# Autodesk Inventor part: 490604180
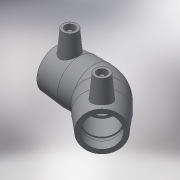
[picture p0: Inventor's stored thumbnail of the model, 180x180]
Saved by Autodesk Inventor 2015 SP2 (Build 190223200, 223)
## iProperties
Created: 2017-06
Part Number: 490604180
Material: Generic
Description: PLASSON 45° ELBOW 180
Document SubType Name: Modeling
Designer: KIM
Mass: 55.0731 g
Surface Area: 148.067 cm^2
Volume: 55.0731 cm^3
Density: 1 g/cm^3
Appearance: Default
Author: KIM
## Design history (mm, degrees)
derived "490604.ipt"
feature "Solid1::490604.ipt"
tag "TaggingFeature1"
body "Solid1"
other parameters: "d2" = 244, "d4" = 108.5, "d5" = 219.6, "d8" = 168 deg, "d10" = 42, "d11" = 14, "d14" = 17.6296, "d19" = 3.52592, "d20" = 168 deg, "d22" = 224.48, "d23" = 244, "d24" = 217.7456, "d29" = 114, "d30" = 15, "d31" = 151.9, "d34" = 5 deg, "d35" = 12, "d39" = 0, "d41" = 4, "d42" = 14, "d43" = 0, "d44" = 9.6, "d45" = 4.8, "d46" = 6, "d47" = 0, "d50" = 153, "d51" = 42, "d52" = 105, "d54" = 135 deg, "d67" = 45 deg, "d71" = 135 deg, "d75" = 12.2, "d82" = 45 deg, "d83" = 105, "d84" = 219.6, "d86" = 109.8, "d87" = 135 deg, "d88" = 434, "d90" = 105, "d91" = 0, "d92" = 105, "d93" = 0, "d94" = 135 deg, "d95" = 112.24, "d98" = 434, "d99" = 143.22, "d101" = 3, "d102" = 0, "d103" = 3, "d104" = 0, "d105" = 30.45, "d106" = 7.6125, "L_" = 434, "L_1" = 105, "D_" = 244, "A_" = 114, "d_2" = 12
